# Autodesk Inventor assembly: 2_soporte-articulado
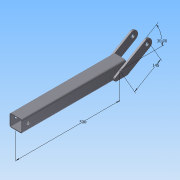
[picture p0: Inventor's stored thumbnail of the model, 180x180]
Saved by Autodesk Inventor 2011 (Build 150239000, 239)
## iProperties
Created: 2020-12
Part Number: 2_soporte-articulado
Document SubType Name: Assembly
Designer: PC
Mass: 4310.49 g
Surface Area: 2534.62 cm^2
Volume: 548.408 cm^3
Density: 7.86 g/cm^3
_SolveAssemblyDoc: Frame Generator Solve Assembly
_Version: 15.0.0
Author: PC
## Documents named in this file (3)
- C:\Users\PC\Documents\Inventor\workshop-crane-powered-by-drill\2_soporte-articulado.iam
- C:\Users\PC\Documents\Inventor\workshop-crane-powered-by-drill\2_soporte-articulado_esqueleto.ipt
- C:\Users\PC\Documents\Inventor\workshop-crane-powered-by-drill\2_soporte-articulado\Frame\Frame0001.iam
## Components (2 placed, 2 different names)
1. 2_soporte-articulado_esqueleto:1
2. Frame0001:1 [sub-assembly]
